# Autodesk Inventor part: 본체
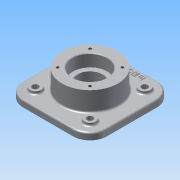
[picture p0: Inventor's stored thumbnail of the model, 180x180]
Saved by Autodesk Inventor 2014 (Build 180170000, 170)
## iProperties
Created: 2015-09
Part Number: 본체
Material: 알루미늄 6061
Document SubType Name: Modeling
Designer: study
Density: 2.71 g/cm^3
Appearance: 알루미늄 - 평지
Mass: 1476.11 g
Surface Area: 799.597 cm^2
Volume: 544.69 cm^3
Author: study
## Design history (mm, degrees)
sketch "스케치1"
  geometry: L1 (-75, 75)-(75, 75); L2 (75, 75)-(75, -75); L3 (75, -75)-(-75, -75); L4 (-75, -75)-(-75, 75); L5 (-75, 75)-(75, -75); L6 (75, 75)-(-75, -75); 1 further point
  constraints: 12 end point, 2 midpoint, 2 parallel, 1 horizontal, 1 perpendicular
  dimensions: "d0" = 150 distance of L1.start L1.end; "d1" = 150 distance of L1.end L2.end
extrude "돌출1" new body sketch "스케치1" distance "d2" = 12; taper "d3" = 0 deg
node "작업 평면1"
sketch "스케치3"
  geometry: C1 r 50 at (0, 0); 1 further point
  constraints: 1 centre point, 1 coincident
  dimensions: "d5" = 100 diameter of C1
extrude "돌출2" join sketch "스케치3" distance "d6" = 70; taper "d7" = 0 deg
sketch "스케치4"
  geometry: C1 r 50 at (0, 0) reference
hole "구멍1" sketch "스케치4" at (0, 0) diameter "d8" = 45; stored, may be unused: countersink angle "d12" = 90 deg, drill point angle "d14" = 0 deg; dims "d9" = 6, "d10" = 62, "d11" = 22, "d13" = 48
sketch "스케치5"
  geometry: C1 r 50 at (0, 0) reference
hole "구멍2" sketch "스케치5" at (0, 0) diameter "d15" = 45; stored, may be unused: countersink angle "d19" = 90 deg, drill point angle "d21" = 0 deg; dims "d16" = 6, "d17" = 62, "d18" = 22, "d20" = 48
sketch "스케치6"
  geometry: L1 (0, 41)-(0, 0); C1 r 31 at (0, 0) reference; C2 r 50 at (0, 0) reference; A1 r 41 centre (0, 0) between (0, 41) and (-28.991, 28.991)
  constraints: 2 end point, 2 point on circle, 1 centre point, 1 coincident, 1 vertical
  dimensions: "d22" = 82 diameter of A1; "d23" = 45 deg dimension on C1.centre A1.end L1.start
hole "구멍3" sketch "스케치6" at (-28.991, 28.991) diameter "d24" = 4.917; stored, may be unused: countersink angle "d28" = 90 deg, drill point angle "d30" = 118 deg; dims "d25" = 10, "d26" = 62, "d27" = 22, "d29" = 13
node "작업 평면2"
fillet "모깎기1" dims "d34" = 30
sketch "스케치7"
  geometry: L1 (-49, 49)-(49, 49); L2 (49, 49)-(49, -49); L3 (49, -49)-(-49, -49); L4 (-49, -49)-(-49, 49); L5 (-49, 49)-(49, -49); L6 (49, 49)-(-49, -49); C1 r 50 at (0, 0) reference; C2 r 10 at (-49, 49); C3 r 10 at (-49, -49); C4 r 10 at (49, -49); C5 r 10 at (49, 49); C6 r 5.5 at (-49, -49); C7 r 5.5 at (-49, 49); C8 r 5.5 at (49, 49); C9 r 5.5 at (49, -49); 1 further point
  constraints: 12 end point, 9 coincident, 8 centre point, 6 equal radius, 2 midpoint, 2 parallel, 1 horizontal, 1 perpendicular
  dimensions: "d35" = 98 distance of L1.start L1.end; "d36" = 98 distance of L1.end L2.end; "d37" = 20 diameter of C2; "d38" = 11 diameter of C7
extrude "돌출3" join sketch "스케치7" distance "d39" = 5; taper "d40" = 0 deg
extrude "돌출4" cut sketch "스케치7" distance "d41" = 31.25; taper "d42" = 0 deg
sketch "스케치8"
  geometry: C1 r 50 at (0, 0) reference; 1 further point
  constraints: 1 vertical alignment, 1 other
  dimensions: "d43" = 65 distance of C1.centre point (0, 65)
feature "엠보싱1" sketch "스케치8" dims "d44" = 1, "d45" = 0
fillet "모깎기2" dims "d46" = 0.3, "d47" = 3
chamfer "모따기1" distance "d48" = 1; stored, may be unused: second distance "d49" = 2, angle "d50" = 45 deg
node "솔리드1"
pattern_circular "원형 패턴1" dims angle "d32" = 360 deg
mirror "대칭1"
other parameters: "d4" = 23
